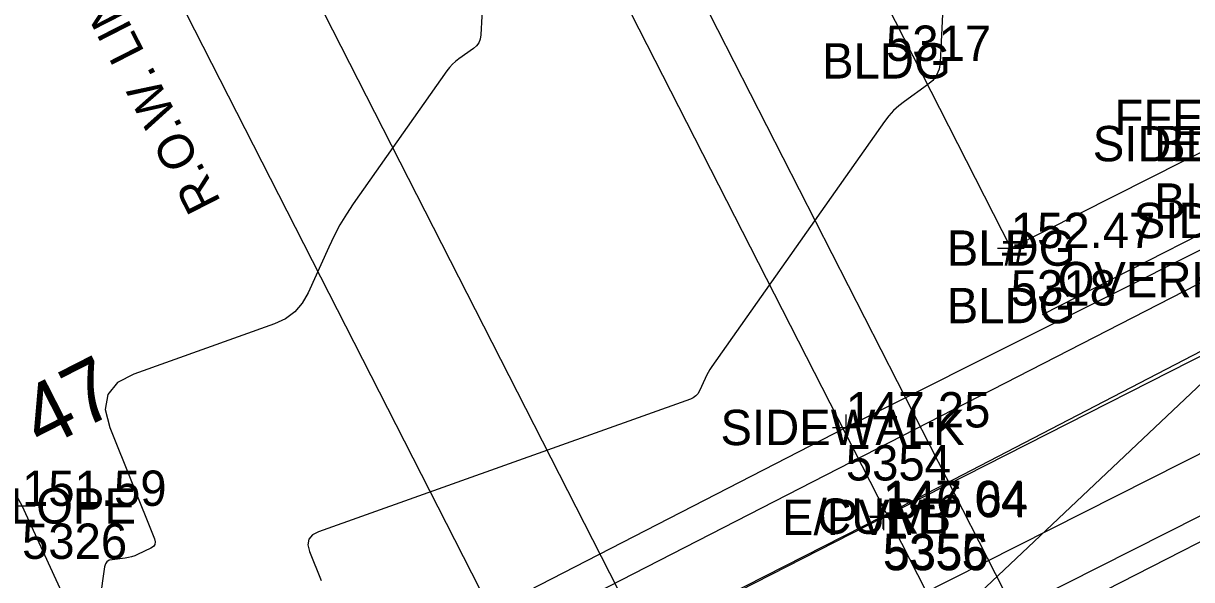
# Model space of a CAD drawing. Extents: x 13482495 to 13483389, y 311646 to 312209.
# Drawn here: x 13482861.1 to 13482966.8, y 311929.4 to 311979.8 of the extents above; entities that cross this region are included whole.
import ezdxf

# ---------------------------------------------------------------- set-up
doc = ezdxf.new("R2010")
doc.units = 0
for name, color, linetype in [('V-BLDG-IDEN', 7, 'Continuous'), ('V-BLDG-OTLN', 7, 'Continuous'), ('V-COMM-UNDR', 7, 'Continuous'), ('V-DEMO-PVMT', 7, 'Continuous'), ('V-NGAS-MAIN', 7, 'Continuous'), ('V-PROP-IDEN', 7, 'Continuous'), ('V-PROP-RWAY', 7, 'Continuous'), ('V-PROP-RWAY-IDEN', 7, 'Continuous'), ('V-PVMT-CNTR', 7, 'Continuous'), ('V-PVMT-SPOT', 7, 'Continuous'), ('V-SITE-SPOT', 7, 'Continuous'), ('V-STRM-MAIN', 7, 'Continuous'), ('V-SURV-PNTS', 7, 'Continuous'), ('V-TOPO-DRAN-SPOT', 7, 'Continuous'), ('V-TOPO-DRAN-TOP', 7, 'Continuous'), ('V-TOPO-LINE-IDEN', 7, 'Continuous'), ('V-TOPO-MAJR', 7, 'Continuous'), ('V-TOPO-MINR', 7, 'Continuous'), ('V-UTIL-OVHD-DEMO', 7, 'Continuous'), ('V-UTIL-UNDR', 7, 'Continuous')]:
    doc.layers.add(name, color=color, linetype=linetype)

msp = doc.modelspace()

# ---------------------------------------------------------------- linework, layer by layer
at = {"layer": 'V-BLDG-OTLN'}
msp.add_lwpolyline([(13482939.17, 311981.6), (13482950.47, 311959.45), (13482969.24, 311968.91)], dxfattribs=at)
at = {"layer": 'V-COMM-UNDR'}
for points in [[(13482638.43, 311773.22), (13482816.88, 311864.74), (13483031.64, 311973.19), (13483313.84, 312119.91)], [(13482816.88, 311864.74), (13482828.02, 311864.74), (13483025.25, 311964.29), (13483031.64, 311973.19)]]:
    msp.add_lwpolyline(points, dxfattribs=at)
at = {"layer": 'V-DEMO-PVMT'}
for points in [[(13482810.45, 311869.62), (13482828.2, 311878.52), (13482836.75, 311882.9), (13482845.2, 311887.23), (13482890.99, 311910.62), (13482938.94, 311935.08), (13482981.59, 311956.77), (13482985.02, 311958.72), (13483004.59, 311968.98)], [(13482811.18, 311879.64), (13482827.58, 311888.04), (13482845.28, 311897.19), (13482887.08, 311918.5), (13482898.26, 311924.03), (13482935.53, 311943.21), (13482972.95, 311961.95)], [(13482841.13, 311891.33), (13482843.09, 311889.56), (13482845.98, 311887.8), (13482890.92, 311910.79), (13482938.88, 311935.18), (13482977.41, 311955.15), (13482979.85, 311956.23)]]:
    msp.add_lwpolyline(points, dxfattribs=at)
at = {"layer": 'V-NGAS-MAIN'}
msp.add_lwpolyline([(13482633.57, 311784.98), (13482635.76, 311786.1), (13483013.72, 311979.94), (13483125.92, 312033.23), (13483152.95, 312055.23), (13483267.21, 312112.66)], dxfattribs=at)
at = {"layer": 'V-PROP-RWAY'}
msp.add_line((13482953.35, 311953.43), (13483318.62, 312139.79), dxfattribs=at)
at = {"layer": 'V-PVMT-CNTR'}
msp.add_lwpolyline([(13482583.66, 311737.16), (13482615.84, 311753.6), (13482631.76, 311761.33), (13482644.15, 311768.11), (13482660.2, 311776.18), (13482708.88, 311801.22), (13482756.86, 311825.71), (13482802.86, 311849.14), (13482850.91, 311873.11), (13482897.46, 311897.25), (13482945.27, 311921.45), (13482988.06, 311943.31), (13483031.89, 311965.62), (13483078.61, 311989.65), (13483123.69, 312012.73), (13483173.43, 312038.09), (13483222.97, 312063.09), (13483269.03, 312086.57), (13483297.77, 312101.09)], dxfattribs=at)
at = {"layer": 'V-PVMT-SPOT'}
for p, q in [((13482935.53, 311944.37), (13482935.53, 311942.05)), ((13482934.33, 311943.21), (13482936.73, 311943.21)), ((13482938.88, 311936.34), (13482938.88, 311934.02)), ((13482938.94, 311936.24), (13482938.94, 311933.92)), ((13482937.68, 311935.18), (13482940.08, 311935.18)), ((13482937.74, 311935.08), (13482940.14, 311935.08))]:
    msp.add_line(p, q, dxfattribs=at)
at = {"layer": 'V-SITE-SPOT'}
for p, q in [((13482950.47, 311960.61), (13482950.47, 311958.29)), ((13482949.27, 311959.45), (13482951.67, 311959.45))]:
    msp.add_line(p, q, dxfattribs=at)
at = {"layer": 'V-STRM-MAIN'}
msp.add_line((13482903.65, 312005.08), (13482965.15, 311884.57), dxfattribs=at)
at = {"layer": 'V-TOPO-DRAN-SPOT'}
msp.add_line((13482859.73, 311936.11), (13482862.13, 311936.11), dxfattribs=at)
at = {"layer": 'V-TOPO-DRAN-TOP'}
msp.add_lwpolyline([(13482870.81, 311913.54), (13482867.94, 311920.87), (13482860.93, 311936.11), (13482846.94, 311961.31), (13482837.05, 311982.68)], dxfattribs=at)
at = {"layer": 'V-TOPO-MAJR'}
msp.add_lwpolyline([(13482902.66, 311982.18), (13482902.49, 311978.75), (13482902.43, 311978.38), (13482902.29, 311978.04), (13482902.08, 311977.75), (13482901.8, 311977.51), (13482900.5, 311976.6), (13482900.19, 311976.36), (13482899.9, 311976.09), (13482899.64, 311975.8), (13482899.4, 311975.49), (13482890.93, 311963.46), (13482890.3, 311962.52), (13482889.72, 311961.56), (13482889.19, 311960.56), (13482888.7, 311959.54), (13482886.85, 311955.41), (13482886.31, 311954.46), (13482885.62, 311953.67), (13482884.78, 311953.05), (13482883.79, 311952.58), (13482871.06, 311948.05), (13482869.57, 311947.27), (13482868.71, 311946.2), (13482868.47, 311944.85), (13482868.87, 311943.21), (13482872.92, 311933.13), (13482872.98, 311932.85), (13482872.95, 311932.62), (13482872.82, 311932.42), (13482872.58, 311932.27), (13482871.4, 311931.7), (13482871.13, 311931.59), (13482870.85, 311931.49), (13482870.56, 311931.43), (13482870.27, 311931.38), (13482869.09, 311931.24), (13482868.82, 311931.18), (13482868.62, 311931.05), (13482868.48, 311930.85), (13482868.41, 311930.59), (13482867.54, 311924.63)], dxfattribs=at)
at = {"layer": 'V-TOPO-MINR'}
msp.add_lwpolyline([(13482944.36, 311981.86), (13482944.07, 311976.25), (13482943.97, 311975.64), (13482943.75, 311975.1), (13482943.41, 311974.62), (13482942.94, 311974.22), (13482940.83, 311972.73), (13482940.32, 311972.33), (13482939.85, 311971.9), (13482939.42, 311971.43), (13482939.02, 311970.92), (13482923.4, 311948.72), (13482923.22, 311948.46), (13482923.07, 311948.2), (13482922.92, 311947.93), (13482922.79, 311947.65), (13482922.28, 311946.53), (13482922.14, 311946.27), (13482921.95, 311946.06), (13482921.72, 311945.89), (13482921.45, 311945.76), (13482887.78, 311933.77), (13482887.23, 311933.48), (13482886.91, 311933.09), (13482886.82, 311932.58), (13482886.97, 311931.98), (13482888.03, 311929.35)], dxfattribs=at)
at = {"layer": 'V-UTIL-OVHD-DEMO'}
msp.add_lwpolyline([(13482892.56, 311876.17), (13482977.71, 311956.6), (13483118.7, 312029.55)], dxfattribs=at)
at = {"layer": 'V-UTIL-UNDR'}
for p, q in [((13483035.2, 311761.22), (13482873.76, 312077.63)), ((13483006.32, 311749.37), (13482848.01, 312059.67)), ((13482993.67, 311749.72), (13482839.75, 312051.39))]:
    msp.add_line(p, q, dxfattribs=at)

# ---------------------------------------------------------------- texts
at = {"layer": 'V-BLDG-IDEN'}
msp.add_text('FFE 146.63', height=3.2, dxfattribs=at).set_placement((13482959.86, 311969.68))
at = {"layer": 'V-PROP-IDEN'}
msp.add_text('47', height=5.6, rotation=27.0313, dxfattribs=at).set_placement((13482862.68, 311941.13))
at = {"layer": 'V-PROP-RWAY-IDEN'}
msp.add_text('R.O.W. LINE', height=3.2, rotation=117.0313, dxfattribs=at).set_placement((13482878.99, 311963.64))
at = {"layer": 'V-PVMT-SPOT'}
for s, p in [('147.25', (13482935.53, 311943.21)), ('147.04', (13482938.88, 311935.18)), ('146.64', (13482938.94, 311935.08))]:
    msp.add_text(s, height=3.2, dxfattribs=at).set_placement(p)
at = {"layer": 'V-SITE-SPOT'}
msp.add_text('152.47', height=3.2, dxfattribs=at).set_placement((13482950.47, 311959.45))
at = {"layer": 'V-SURV-PNTS'}
for s, p in [('5317', (13482939.17, 311976.4)), ('5318', (13482950.47, 311954.25)), ('5354', (13482935.53, 311938.41)), ('5326', (13482860.93, 311931.31)), ('5355', (13482938.88, 311930.38)), ('5356', (13482938.94, 311930.28))]:
    msp.add_text(s, height=3.2, dxfattribs=at).set_placement(p)
at = {"layer": 'V-TOPO-DRAN-SPOT'}
msp.add_text('151.59', height=3.2, dxfattribs=at).set_placement((13482860.93, 311936.11))
at = {"layer": 'V-TOPO-LINE-IDEN'}
for s, p in [('BLDG', (13482933.38, 311974.8)), ('SIDEWALK', (13482957.89, 311967.31)), ('BLDG', (13482963.44, 311967.31)), ('BLDG', (13482963.44, 311962.11)), ('SIDEWALK', (13482961.6, 311960.35)), ('BLDG', (13482944.67, 311957.85)), ('#', (13482949.65, 311957.85)), ('OVERHEAD UTILITY', (13482954.71, 311955)), ('BLDG', (13482944.67, 311952.65)), ('SIDEWALK', (13482924.18, 311941.61)), ('TOP SLOPE', (13482846.99, 311934.51)), ('E/PVMT', (13482929.75, 311933.48)), ('CURB', (13482932.94, 311933.58))]:
    msp.add_text(s, height=3.2, dxfattribs=at).set_placement(p)

doc.saveas('drawing.dxf')
